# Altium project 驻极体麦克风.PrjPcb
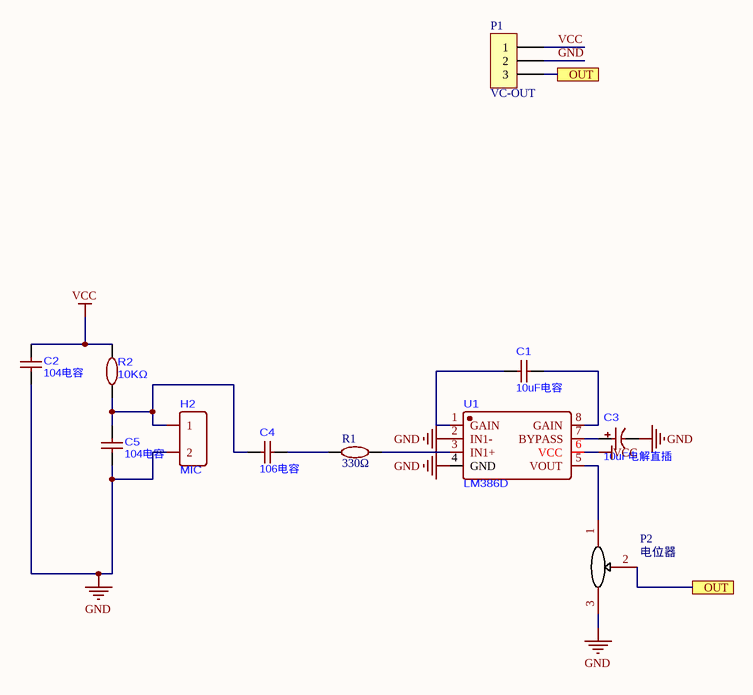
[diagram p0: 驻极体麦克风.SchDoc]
1 sheet, 11 parts. Net scope: flat (ports and power ports of the same name join across sheets).
Board file: 驻极体麦克风.PcbDoc

## Sheet 驻极体麦克风.SchDoc
size A4; SheetNumber: 1; SheetTotal: 1

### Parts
C1  10uF电容  [C0805]
C2  104电容  [C0805]
C3  10uF电解直插  [CAP-TH_BD4.0-P1.50-D0.8-FD]
C4  106电容  [C0805]
C5  104电容  [C0805]
H2  MIC  [HDR-TH_2P-P2.54-V-M-1]
P1  VC-OUT  [VC-OUT]
P2  电位器  [电位器]
R1  330Ω  [R0805]
R2  10KΩ  [R0805]
U1  LM386D  [SOP-8_L4.9-W3.9-P1.27-LS6.0-BL]

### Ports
OUT

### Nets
GND: C2.1 C3.2 C5.1 H2.2 P1.2 P2.3 U1.2(IN1-) U1.4(GND)
VCC: C2.2 P1.1 R2.2 U1.6(VCC)
NetC1_1: C1.1 U1.1(GAIN)
NetC1_2: C1.2 U1.8(GAIN)
NetC3_1: C3.1 U1.7(BYPASS)
NetC4_1: C4.1 C5.2 H2.1 R2.1
NetC4_2: C4.2 R1.1
NetP1_3: P1.3 P2.2 ; port OUT
NetP2_1: P2.1 U1.5(VOUT)
NetR1_2: R1.2 U1.3(IN1+)

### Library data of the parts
C4 = 104电容
H2 = 2p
